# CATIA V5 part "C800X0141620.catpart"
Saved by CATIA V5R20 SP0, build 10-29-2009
Part number: C800X0141620
Source: Unknown
Property "A": "30"
Property "ARTICLENO": "C800X0141620"
Property "B": "13"
Property "BOMINFO": "C800X0141620"
Property "C": "46"
Property "CA": "C800X0141620"
Property "D1": "38"
Property "DES": "ROTATING EYEBOLT WITH RING Ton 1,4 M16x20"
Property "E": "50"
Property "H": "105"
Property "L": "20"
Property "LINA": "C800X0141620"
Property "NB": "C800X0141620"
Property "NBSYN": "$CODE."
Property "NN": "C800X"
Property "NT": "Rotating eyebolt with ring"
Property "SIZE": "M16"
Property "SUPPLIER": "CF"
Property "SW": "30"
Property "WEIGHT": "530"
Property "WLL": "1.40"
Bounding box of the stored display mesh (mm): x -27.837 to 28, y -20 to 117.837, z -19 to 19
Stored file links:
  C:\Users\Utente\Desktop\3D files 800X\C800X0141620.catpart

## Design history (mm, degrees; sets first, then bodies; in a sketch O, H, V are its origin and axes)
Body1 "Geometry.1" (main body)
  Solid1 "C800X0141620.catpart": solid without history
